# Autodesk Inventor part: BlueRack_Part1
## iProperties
Shininess: 64.0
Length Units: 11272
Angle Units: 11279
Time Units: 11290
Mass Units: 11286
Length Display Precision: 3
Angle Display Precision: 2
Compacted: True
Part Number: BlueRack_Part1
Document SubType Name: Modeling
Created: 2004-12
Designer: John Blackburn
Material: Steel, Mild
Manufacturer: Standard
Standards Organization: Custom
Density: 0.0
Volumn: 0.0
Area: 0.0
PropertySet Name: Model Information
Control State: 0
Master: False
Checked Out: False
Author: John Blackburn
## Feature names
1. Extrusion1
2. Extrusion3
3. Extrusion4
